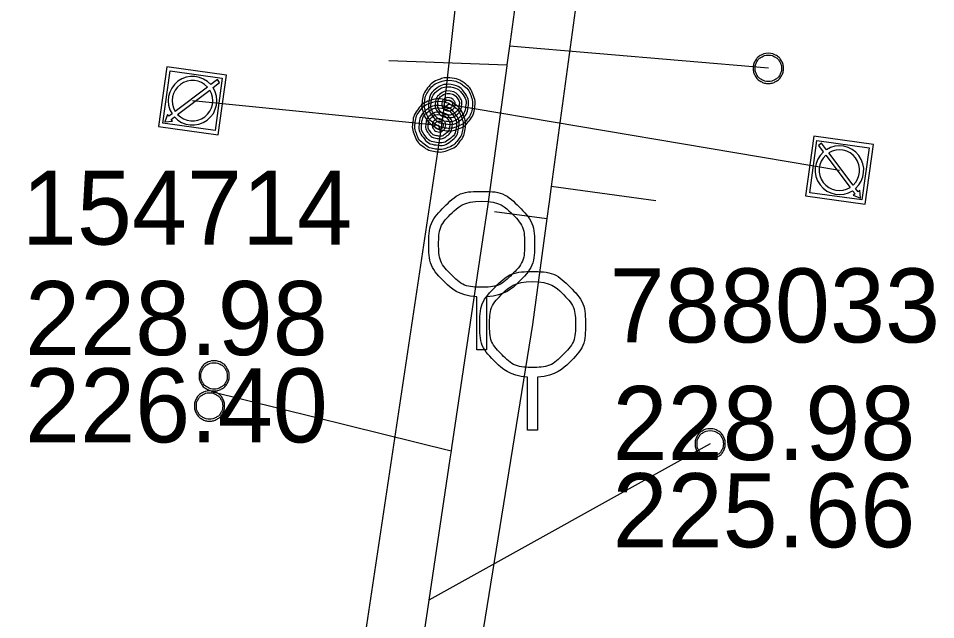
# Model space of a CAD drawing. Extents: x -595129 to -593591, y -1168385 to -1166898.
# Drawn here: x -594632.2 to -594614.85, y -1167115.28 to -1167103.91 of the extents above; entities that cross this region are included whole.
import ezdxf

# ---------------------------------------------------------------- set-up
doc = ezdxf.new("R2010")
doc.units = 0
for name, color, linetype in [('Default', 7, 'Continuous'), ('Identifikace', 7, 'Continuous'), ('Kanalizační přípojka', 7, 'Continuous'), ('Kanalizační stoka', 7, 'Continuous'), ('Kanalizační šachta', 7, 'Continuous'), ('Popis šachty', 7, 'Continuous'), ('V Odběrné místo', 7, 'Continuous'), ('V Přípojka', 7, 'Continuous'), ('V Řad', 7, 'Continuous')]:
    doc.layers.add(name, color=color, linetype=linetype)

msp = doc.modelspace()

# ---------------------------------------------------------------- linework, layer by layer
at = {"layer": 'Default'}
for points in [[(-594618.01, -1167104.565), (-594617.938, -1167104.565), (-594617.87, -1167104.602), (-594617.802, -1167104.638), (-594617.764, -1167104.707), (-594617.725, -1167104.776), (-594617.725, -1167104.85), (-594617.725, -1167104.924), (-594617.763, -1167104.992), (-594617.8, -1167105.06), (-594617.868, -1167105.097), (-594617.936, -1167105.135), (-594618.01, -1167105.135), (-594618.084, -1167105.135), (-594618.152, -1167105.097), (-594618.22, -1167105.06), (-594618.257, -1167104.992), (-594618.295, -1167104.924), (-594618.295, -1167104.85), (-594618.295, -1167104.776), (-594618.257, -1167104.707), (-594618.218, -1167104.638), (-594618.15, -1167104.602), (-594618.082, -1167104.565), (-594618.01, -1167104.565)], [(-594618.01, -1167104.601), (-594618.073, -1167104.601), (-594618.133, -1167104.633), (-594618.193, -1167104.665), (-594618.226, -1167104.725), (-594618.259, -1167104.785), (-594618.259, -1167104.85), (-594618.259, -1167104.915), (-594618.227, -1167104.974), (-594618.194, -1167105.033), (-594618.134, -1167105.066), (-594618.075, -1167105.099), (-594618.01, -1167105.099), (-594617.945, -1167105.099), (-594617.886, -1167105.066), (-594617.826, -1167105.033), (-594617.793, -1167104.974), (-594617.761, -1167104.915), (-594617.761, -1167104.85), (-594617.761, -1167104.785), (-594617.794, -1167104.725), (-594617.828, -1167104.665), (-594617.888, -1167104.633), (-594617.947, -1167104.601), (-594618.01, -1167104.601)], [(-594623.991, -1167105.034), (-594623.866, -1167105.051), (-594623.756, -1167105.132), (-594623.647, -1167105.212), (-594623.597, -1167105.341), (-594623.546, -1167105.47), (-594623.564, -1167105.599), (-594623.582, -1167105.728), (-594623.664, -1167105.837), (-594623.746, -1167105.946), (-594623.873, -1167105.994), (-594624.001, -1167106.043), (-594624.13, -1167106.025), (-594624.258, -1167106.007), (-594624.367, -1167105.925), (-594624.476, -1167105.843), (-594624.525, -1167105.716), (-594624.574, -1167105.589), (-594624.556, -1167105.461), (-594624.537, -1167105.331), (-594624.454, -1167105.221), (-594624.371, -1167105.111), (-594624.244, -1167105.064), (-594624.116, -1167105.016), (-594623.991, -1167105.034)], [(-594623.997, -1167105.08), (-594624.111, -1167105.064), (-594624.226, -1167105.107), (-594624.342, -1167105.15), (-594624.417, -1167105.25), (-594624.493, -1167105.349), (-594624.509, -1167105.467), (-594624.526, -1167105.584), (-594624.481, -1167105.699), (-594624.437, -1167105.814), (-594624.338, -1167105.888), (-594624.24, -1167105.962), (-594624.123, -1167105.979), (-594624.006, -1167105.995), (-594623.891, -1167105.951), (-594623.775, -1167105.906), (-594623.701, -1167105.808), (-594623.627, -1167105.71), (-594623.611, -1167105.593), (-594623.594, -1167105.475), (-594623.64, -1167105.359), (-594623.686, -1167105.242), (-594623.785, -1167105.169), (-594623.884, -1167105.096), (-594623.997, -1167105.08)], [(-594624.009, -1167105.158), (-594623.852, -1167105.18), (-594623.76, -1167105.304), (-594623.667, -1167105.428), (-594623.688, -1167105.582), (-594623.71, -1167105.736), (-594623.834, -1167105.829), (-594623.958, -1167105.923), (-594624.113, -1167105.901), (-594624.266, -1167105.88), (-594624.36, -1167105.756), (-594624.453, -1167105.632), (-594624.432, -1167105.478), (-594624.41, -1167105.324), (-594624.287, -1167105.23), (-594624.164, -1167105.136), (-594624.009, -1167105.158)], [(-594624.015, -1167105.203), (-594624.151, -1167105.184), (-594624.259, -1167105.266), (-594624.367, -1167105.348), (-594624.386, -1167105.483), (-594624.405, -1167105.618), (-594624.323, -1167105.726), (-594624.242, -1167105.835), (-594624.106, -1167105.854), (-594623.971, -1167105.873), (-594623.863, -1167105.791), (-594623.754, -1167105.709), (-594623.735, -1167105.574), (-594623.717, -1167105.439), (-594623.798, -1167105.331), (-594623.879, -1167105.222), (-594624.015, -1167105.203)], [(-594624.171, -1167105.433), (-594624.046, -1167105.45), (-594623.936, -1167105.531), (-594623.827, -1167105.611), (-594623.777, -1167105.74), (-594623.726, -1167105.869), (-594623.744, -1167105.998), (-594623.762, -1167106.127), (-594623.844, -1167106.236), (-594623.926, -1167106.345), (-594624.053, -1167106.393), (-594624.181, -1167106.442), (-594624.31, -1167106.424), (-594624.438, -1167106.406), (-594624.547, -1167106.324), (-594624.656, -1167106.242), (-594624.705, -1167106.115), (-594624.754, -1167105.988), (-594624.736, -1167105.86), (-594624.717, -1167105.73), (-594624.634, -1167105.62), (-594624.551, -1167105.51), (-594624.424, -1167105.463), (-594624.296, -1167105.415), (-594624.171, -1167105.433)], [(-594624.026, -1167105.282), (-594623.922, -1167105.296), (-594623.86, -1167105.379), (-594623.798, -1167105.462), (-594623.812, -1167105.565), (-594623.827, -1167105.667), (-594623.909, -1167105.73), (-594623.992, -1167105.792), (-594624.095, -1167105.777), (-594624.197, -1167105.763), (-594624.26, -1167105.68), (-594624.322, -1167105.598), (-594624.308, -1167105.495), (-594624.293, -1167105.392), (-594624.211, -1167105.33), (-594624.129, -1167105.267), (-594624.026, -1167105.282)], [(-594624.032, -1167105.328), (-594624.116, -1167105.316), (-594624.183, -1167105.366), (-594624.25, -1167105.417), (-594624.262, -1167105.501), (-594624.273, -1167105.584), (-594624.223, -1167105.652), (-594624.172, -1167105.719), (-594624.089, -1167105.73), (-594624.005, -1167105.742), (-594623.938, -1167105.691), (-594623.871, -1167105.641), (-594623.859, -1167105.557), (-594623.847, -1167105.473), (-594623.898, -1167105.406), (-594623.948, -1167105.339), (-594624.032, -1167105.328)], [(-594624.043, -1167105.406), (-594623.991, -1167105.413), (-594623.96, -1167105.454), (-594623.929, -1167105.496), (-594623.936, -1167105.547), (-594623.943, -1167105.598), (-594623.985, -1167105.629), (-594624.026, -1167105.661), (-594624.078, -1167105.653), (-594624.129, -1167105.646), (-594624.16, -1167105.605), (-594624.191, -1167105.563), (-594624.184, -1167105.512), (-594624.177, -1167105.461), (-594624.136, -1167105.43), (-594624.094, -1167105.398), (-594624.043, -1167105.406)], [(-594624.177, -1167105.479), (-594624.291, -1167105.463), (-594624.406, -1167105.506), (-594624.522, -1167105.549), (-594624.597, -1167105.649), (-594624.673, -1167105.748), (-594624.689, -1167105.866), (-594624.706, -1167105.983), (-594624.661, -1167106.098), (-594624.617, -1167106.213), (-594624.518, -1167106.287), (-594624.42, -1167106.361), (-594624.303, -1167106.378), (-594624.186, -1167106.394), (-594624.071, -1167106.35), (-594623.955, -1167106.305), (-594623.881, -1167106.207), (-594623.807, -1167106.109), (-594623.791, -1167105.992), (-594623.774, -1167105.874), (-594623.82, -1167105.758), (-594623.866, -1167105.641), (-594623.965, -1167105.568), (-594624.064, -1167105.495), (-594624.177, -1167105.479)], [(-594624.189, -1167105.557), (-594624.032, -1167105.579), (-594623.94, -1167105.703), (-594623.847, -1167105.827), (-594623.868, -1167105.981), (-594623.89, -1167106.135), (-594624.014, -1167106.228), (-594624.138, -1167106.322), (-594624.293, -1167106.3), (-594624.446, -1167106.279), (-594624.54, -1167106.155), (-594624.633, -1167106.031), (-594624.612, -1167105.877), (-594624.59, -1167105.723), (-594624.467, -1167105.629), (-594624.344, -1167105.535), (-594624.189, -1167105.557)], [(-594624.195, -1167105.602), (-594624.331, -1167105.583), (-594624.439, -1167105.665), (-594624.547, -1167105.747), (-594624.566, -1167105.882), (-594624.585, -1167106.017), (-594624.503, -1167106.125), (-594624.422, -1167106.234), (-594624.286, -1167106.253), (-594624.151, -1167106.272), (-594624.043, -1167106.19), (-594623.934, -1167106.108), (-594623.915, -1167105.973), (-594623.897, -1167105.838), (-594623.978, -1167105.73), (-594624.059, -1167105.621), (-594624.195, -1167105.602)], [(-594624.05, -1167105.452), (-594624.082, -1167105.448), (-594624.107, -1167105.467), (-594624.133, -1167105.486), (-594624.138, -1167105.519), (-594624.142, -1167105.551), (-594624.123, -1167105.576), (-594624.103, -1167105.602), (-594624.071, -1167105.607), (-594624.038, -1167105.612), (-594624.013, -1167105.592), (-594623.987, -1167105.572), (-594623.983, -1167105.54), (-594623.978, -1167105.507), (-594623.998, -1167105.482), (-594624.017, -1167105.457), (-594624.05, -1167105.452)], [(-594624.206, -1167105.681), (-594624.102, -1167105.695), (-594624.04, -1167105.778), (-594623.978, -1167105.861), (-594623.992, -1167105.964), (-594624.007, -1167106.066), (-594624.089, -1167106.129), (-594624.172, -1167106.191), (-594624.275, -1167106.176), (-594624.377, -1167106.162), (-594624.44, -1167106.079), (-594624.502, -1167105.997), (-594624.488, -1167105.894), (-594624.473, -1167105.791), (-594624.391, -1167105.729), (-594624.309, -1167105.666), (-594624.206, -1167105.681)], [(-594624.212, -1167105.727), (-594624.296, -1167105.715), (-594624.363, -1167105.765), (-594624.43, -1167105.816), (-594624.442, -1167105.9), (-594624.453, -1167105.983), (-594624.403, -1167106.051), (-594624.352, -1167106.118), (-594624.269, -1167106.129), (-594624.185, -1167106.141), (-594624.118, -1167106.09), (-594624.051, -1167106.04), (-594624.039, -1167105.956), (-594624.027, -1167105.872), (-594624.078, -1167105.805), (-594624.128, -1167105.738), (-594624.212, -1167105.727)], [(-594624.223, -1167105.805), (-594624.171, -1167105.812), (-594624.14, -1167105.853), (-594624.109, -1167105.895), (-594624.116, -1167105.946), (-594624.123, -1167105.997), (-594624.165, -1167106.028), (-594624.206, -1167106.06), (-594624.258, -1167106.052), (-594624.309, -1167106.045), (-594624.34, -1167106.004), (-594624.371, -1167105.962), (-594624.364, -1167105.911), (-594624.357, -1167105.86), (-594624.316, -1167105.829), (-594624.274, -1167105.797), (-594624.223, -1167105.805)], [(-594624.23, -1167105.851), (-594624.262, -1167105.847), (-594624.287, -1167105.866), (-594624.313, -1167105.885), (-594624.318, -1167105.918), (-594624.322, -1167105.95), (-594624.303, -1167105.975), (-594624.283, -1167106.001), (-594624.251, -1167106.006), (-594624.218, -1167106.011), (-594624.193, -1167105.991), (-594624.167, -1167105.971), (-594624.163, -1167105.939), (-594624.158, -1167105.906), (-594624.178, -1167105.881), (-594624.197, -1167105.856), (-594624.23, -1167105.851)], [(-594623.526, -1167109.173), (-594623.879, -1167109.144), (-594624.139, -1167108.884), (-594624.432, -1167108.593), (-594624.432, -1167108.179), (-594624.432, -1167107.763), (-594624.142, -1167107.47), (-594623.852, -1167107.177), (-594623.434, -1167107.177), (-594623.014, -1167107.177), (-594622.723, -1167107.47), (-594622.432, -1167107.763), (-594622.432, -1167108.179), (-594622.432, -1167108.593), (-594622.725, -1167108.884), (-594622.983, -1167109.144), (-594623.338, -1167109.173)], [(-594623.434, -1167107.363), (-594623.772, -1167107.363), (-594624.009, -1167107.6), (-594624.246, -1167107.837), (-594624.246, -1167108.175), (-594624.246, -1167108.513), (-594624.009, -1167108.75), (-594623.772, -1167108.988), (-594623.434, -1167108.988), (-594623.096, -1167108.988), (-594622.859, -1167108.75), (-594622.621, -1167108.513), (-594622.621, -1167108.175), (-594622.621, -1167107.837), (-594622.858, -1167107.6), (-594623.094, -1167107.363), (-594623.434, -1167107.363)], [(-594622.563, -1167110.691), (-594622.916, -1167110.662), (-594623.176, -1167110.402), (-594623.469, -1167110.111), (-594623.469, -1167109.697), (-594623.469, -1167109.281), (-594623.179, -1167108.988), (-594622.889, -1167108.695), (-594622.471, -1167108.695), (-594622.051, -1167108.695), (-594621.76, -1167108.988), (-594621.469, -1167109.281), (-594621.469, -1167109.697), (-594621.469, -1167110.111), (-594621.762, -1167110.402), (-594622.02, -1167110.662), (-594622.375, -1167110.691)], [(-594622.471, -1167108.881), (-594622.809, -1167108.881), (-594623.046, -1167109.118), (-594623.283, -1167109.355), (-594623.283, -1167109.693), (-594623.283, -1167110.031), (-594623.046, -1167110.268), (-594622.809, -1167110.506), (-594622.471, -1167110.506), (-594622.133, -1167110.506), (-594621.896, -1167110.268), (-594621.658, -1167110.031), (-594621.658, -1167109.693), (-594621.658, -1167109.355), (-594621.895, -1167109.118), (-594622.131, -1167108.881), (-594622.471, -1167108.881)], [(-594628.493, -1167110.382), (-594628.421, -1167110.382), (-594628.353, -1167110.419), (-594628.285, -1167110.455), (-594628.247, -1167110.524), (-594628.208, -1167110.593), (-594628.208, -1167110.667), (-594628.208, -1167110.741), (-594628.246, -1167110.809), (-594628.283, -1167110.877), (-594628.351, -1167110.914), (-594628.419, -1167110.952), (-594628.493, -1167110.952), (-594628.567, -1167110.952), (-594628.635, -1167110.914), (-594628.703, -1167110.877), (-594628.74, -1167110.809), (-594628.778, -1167110.741), (-594628.778, -1167110.667), (-594628.778, -1167110.593), (-594628.74, -1167110.524), (-594628.701, -1167110.455), (-594628.633, -1167110.419), (-594628.565, -1167110.382), (-594628.493, -1167110.382)], [(-594628.493, -1167110.418), (-594628.556, -1167110.418), (-594628.616, -1167110.45), (-594628.676, -1167110.482), (-594628.709, -1167110.542), (-594628.742, -1167110.602), (-594628.742, -1167110.667), (-594628.742, -1167110.732), (-594628.71, -1167110.791), (-594628.677, -1167110.85), (-594628.617, -1167110.883), (-594628.558, -1167110.916), (-594628.493, -1167110.916), (-594628.428, -1167110.916), (-594628.369, -1167110.883), (-594628.309, -1167110.85), (-594628.276, -1167110.791), (-594628.244, -1167110.732), (-594628.244, -1167110.667), (-594628.244, -1167110.602), (-594628.277, -1167110.542), (-594628.311, -1167110.482), (-594628.371, -1167110.45), (-594628.43, -1167110.418), (-594628.493, -1167110.418)], [(-594628.58, -1167110.951), (-594628.508, -1167110.951), (-594628.44, -1167110.988), (-594628.372, -1167111.024), (-594628.334, -1167111.093), (-594628.295, -1167111.162), (-594628.295, -1167111.236), (-594628.295, -1167111.31), (-594628.333, -1167111.378), (-594628.37, -1167111.446), (-594628.438, -1167111.483), (-594628.506, -1167111.521), (-594628.58, -1167111.521), (-594628.654, -1167111.521), (-594628.722, -1167111.483), (-594628.79, -1167111.446), (-594628.827, -1167111.378), (-594628.865, -1167111.31), (-594628.865, -1167111.236), (-594628.865, -1167111.162), (-594628.827, -1167111.093), (-594628.788, -1167111.024), (-594628.72, -1167110.988), (-594628.652, -1167110.951), (-594628.58, -1167110.951)], [(-594628.58, -1167110.987), (-594628.643, -1167110.987), (-594628.703, -1167111.019), (-594628.763, -1167111.051), (-594628.796, -1167111.111), (-594628.829, -1167111.171), (-594628.829, -1167111.236), (-594628.829, -1167111.301), (-594628.797, -1167111.36), (-594628.764, -1167111.419), (-594628.704, -1167111.452), (-594628.645, -1167111.485), (-594628.58, -1167111.485), (-594628.515, -1167111.485), (-594628.456, -1167111.452), (-594628.396, -1167111.419), (-594628.363, -1167111.36), (-594628.331, -1167111.301), (-594628.331, -1167111.236), (-594628.331, -1167111.171), (-594628.364, -1167111.111), (-594628.398, -1167111.051), (-594628.458, -1167111.019), (-594628.517, -1167110.987), (-594628.58, -1167110.987)], [(-594619.11, -1167111.665), (-594619.038, -1167111.665), (-594618.97, -1167111.702), (-594618.902, -1167111.738), (-594618.864, -1167111.807), (-594618.825, -1167111.876), (-594618.825, -1167111.95), (-594618.825, -1167112.024), (-594618.863, -1167112.092), (-594618.9, -1167112.16), (-594618.968, -1167112.197), (-594619.036, -1167112.235), (-594619.11, -1167112.235), (-594619.184, -1167112.235), (-594619.252, -1167112.197), (-594619.32, -1167112.16), (-594619.357, -1167112.092), (-594619.395, -1167112.024), (-594619.395, -1167111.95), (-594619.395, -1167111.876), (-594619.357, -1167111.807), (-594619.318, -1167111.738), (-594619.25, -1167111.702), (-594619.182, -1167111.665), (-594619.11, -1167111.665)], [(-594619.11, -1167111.701), (-594619.173, -1167111.701), (-594619.233, -1167111.733), (-594619.293, -1167111.765), (-594619.326, -1167111.825), (-594619.359, -1167111.885), (-594619.359, -1167111.95), (-594619.359, -1167112.015), (-594619.327, -1167112.074), (-594619.294, -1167112.133), (-594619.234, -1167112.166), (-594619.175, -1167112.199), (-594619.11, -1167112.199), (-594619.045, -1167112.199), (-594618.986, -1167112.166), (-594618.926, -1167112.133), (-594618.893, -1167112.074), (-594618.861, -1167112.015), (-594618.861, -1167111.95), (-594618.861, -1167111.885), (-594618.894, -1167111.825), (-594618.928, -1167111.765), (-594618.988, -1167111.733), (-594619.047, -1167111.701), (-594619.11, -1167111.701)]]:
    msp.add_open_spline(points, degree=3, dxfattribs=at)
at = {"layer": 'Kanalizační přípojka'}
msp.add_line((-594619.11, -1167111.95), (-594624.429, -1167114.906), dxfattribs=at)
for points in [[(-594618.01, -1167104.85), (-594622.906, -1167104.431)], [(-594625.19, -1167104.7), (-594622.954, -1167104.786)], [(-594620.135, -1167107.356), (-594622.117, -1167107.088)], [(-594623.189, -1167107.557), (-594622.198, -1167107.691)], [(-594628.543, -1167110.963), (-594624.011, -1167112.086)]]:
    msp.add_lwpolyline(points, dxfattribs=at)
at = {"layer": 'Kanalizační stoka'}
for points in [[(-594619.168, -1167077.517), (-594620.191, -1167084.902), (-594620.217, -1167085.092), (-594620.356, -1167086.096), (-594621.235, -1167092.419), (-594621.243, -1167092.478), (-594621.329, -1167093.099), (-594621.47, -1167094.061), (-594621.544, -1167094.588), (-594621.559, -1167094.696), (-594621.85, -1167096.776), (-594621.867, -1167096.895), (-594622.14, -1167098.856), (-594622.151, -1167098.936), (-594622.383, -1167100.593), (-594622.894, -1167104.345), (-594622.906, -1167104.431), (-594622.954, -1167104.786), (-594622.956, -1167104.8), (-594623.319, -1167107.467), (-594623.432, -1167108.177)], [(-594618.369, -1167079.372), (-594618.934, -1167083.55), (-594618.96, -1167083.742), (-594619.152, -1167085.159), (-594619.169, -1167085.288), (-594619.318, -1167086.394), (-594619.363, -1167086.725), (-594620.114, -1167092.278), (-594620.163, -1167092.641), (-594621.116, -1167099.683), (-594621.158, -1167099.994), (-594621.524, -1167102.705), (-594621.553, -1167102.918), (-594622.117, -1167107.088), (-594622.156, -1167107.377), (-594622.198, -1167107.691), (-594622.469, -1167109.695)], [(-594623.432, -1167108.177), (-594624.002, -1167112.025), (-594624.011, -1167112.086), (-594624.033, -1167112.233), (-594624.429, -1167114.906), (-594625.719, -1167123.567), (-594625.744, -1167123.736), (-594625.822, -1167124.258), (-594625.844, -1167124.409), (-594626.141, -1167126.403), (-594626.362, -1167127.89), (-594626.388, -1167128.069), (-594626.57, -1167129.292), (-594626.573, -1167129.315), (-594626.825, -1167131.013), (-594627.663, -1167136.707)], [(-594622.469, -1167109.695), (-594623.816, -1167117.996), (-594623.863, -1167118.283), (-594624.053, -1167119.457), (-594624.101, -1167119.753), (-594624.29, -1167120.918), (-594624.328, -1167121.155), (-594625.261, -1167126.9), (-594625.299, -1167127.137), (-594625.978, -1167131.322), (-594626.013, -1167131.539), (-594626.244, -1167132.961), (-594626.246, -1167132.971), (-594626.81, -1167136.445), (-594626.874, -1167136.84), (-594627.277, -1167139.327), (-594627.291, -1167139.416), (-594627.748, -1167142.23), (-594627.762, -1167142.318), (-594628.962, -1167149.712), (-594628.973, -1167149.781), (-594629.44, -1167152.663), (-594629.442, -1167152.673), (-594630.062, -1167156.493)]]:
    msp.add_lwpolyline(points, dxfattribs=at)
at = {"layer": 'Kanalizační šachta'}
for points in [[(-594623.338, -1167109.173), (-594623.338, -1167110.177), (-594623.526, -1167110.177), (-594623.526, -1167109.173)], [(-594622.375, -1167110.691), (-594622.375, -1167111.695), (-594622.563, -1167111.695), (-594622.563, -1167110.691)]]:
    msp.add_lwpolyline(points, dxfattribs=at)
at = {"layer": 'V Odběrné místo'}
for p, q in [((-594628.618, -1167105.205), (-594629.227, -1167105.664)), ((-594629.184, -1167105.722), (-594628.575, -1167105.262)), ((-594616.406, -1167107.06), (-594616.867, -1167106.451)), ((-594616.923, -1167106.494), (-594616.463, -1167107.103))]:
    msp.add_line(p, q, dxfattribs=at)
for points in [[(-594628.258, -1167104.977), (-594629.387, -1167104.82), (-594629.544, -1167105.949), (-594628.415, -1167106.106)], [(-594628.338, -1167105.038), (-594628.476, -1167106.026), (-594629.464, -1167105.888), (-594629.326, -1167104.9)], [(-594617.151, -1167106.134), (-594617.308, -1167107.263), (-594616.179, -1167107.42), (-594616.022, -1167106.291)], [(-594617.09, -1167106.214), (-594616.102, -1167106.352), (-594616.24, -1167107.34), (-594617.228, -1167107.202)]]:
    msp.add_lwpolyline(points, close=True, dxfattribs=at)
for points in [[(-594628.514, -1167105.215), (-594628.389, -1167105.121), (-594628.432, -1167105.064), (-594628.556, -1167105.158)], [(-594629.288, -1167105.711), (-594629.35, -1167105.758), (-594629.374, -1167105.725), (-594629.428, -1167105.864), (-594629.279, -1167105.851), (-594629.307, -1167105.815), (-594629.245, -1167105.768)], [(-594616.913, -1167106.39), (-594617.007, -1167106.265), (-594617.064, -1167106.308), (-594616.97, -1167106.432)], [(-594616.417, -1167107.164), (-594616.37, -1167107.226), (-594616.403, -1167107.25), (-594616.264, -1167107.304), (-594616.277, -1167107.155), (-594616.313, -1167107.183), (-594616.36, -1167107.121)]]:
    msp.add_lwpolyline(points, dxfattribs=at)
for centre, radius, start, end in [((-594628.901, -1167105.463), 0.46, 41.4816, 212.6367), ((-594628.901, -1167105.463), 0.383, 42.3723, 211.6928), ((-594628.901, -1167105.463), 0.46, 221.5322, 32.5864), ((-594628.901, -1167105.463), 0.383, 222.423, 31.6957), ((-594616.665, -1167106.777), 0.46, 131.4932, 302.6484), ((-594616.665, -1167106.777), 0.46, 311.5439, 122.5981), ((-594616.665, -1167106.777), 0.383, 312.4347, 121.7074), ((-594616.665, -1167106.777), 0.383, 132.3839, 301.7044)]:
    msp.add_arc(centre, radius, start, end, dxfattribs=at)
at = {"layer": 'V Přípojka'}
for points in [[(-594624.21, -1167106.05), (-594624.24, -1167105.929), (-594628.901, -1167105.463)], [(-594624.15, -1167105.6), (-594624.06, -1167105.53), (-594616.665, -1167106.777)]]:
    msp.add_lwpolyline(points, dxfattribs=at)
at = {"layer": 'V Řad'}
msp.add_lwpolyline([(-594620.641, -1167079.706), (-594621.282, -1167084.294), (-594621.49, -1167086.39), (-594622.13, -1167090.96), (-594623.141, -1167097.603), (-594623.691, -1167101.542), (-594624.15, -1167105.6), (-594624.21, -1167106.05), (-594625.836, -1167116.894), (-594625.854, -1167117.021), (-594626.112, -1167118.865), (-594627.094, -1167125.893), (-594627.519, -1167128.934), (-594627.85, -1167131.301), (-594628.024, -1167132.551), (-594628.278, -1167134.289), (-594629.266, -1167141.052), (-594629.36, -1167141.695), (-594630.06, -1167148.16), (-594630.57, -1167151.72), (-594631.97, -1167161.48), (-594632.196, -1167162.18)], dxfattribs=at)

# ---------------------------------------------------------------- texts
at = {"layer": 'Identifikace'}
for s, p in [('154714', (-594632.13, -1167108.183)), ('788033', (-594621.01, -1167110.034))]:
    msp.add_text(s, height=1.4, dxfattribs=at).set_placement(p)
at = {"layer": 'Popis šachty'}
for s, p in [('228.98', (-594632.069, -1167110.274)), ('226.40', (-594632.069, -1167111.924)), ('228.98', (-594620.957, -1167112.258)), ('225.66', (-594620.957, -1167113.908))]:
    msp.add_text(s, height=1.4, dxfattribs=at).set_placement(p)

doc.saveas('drawing.dxf')
